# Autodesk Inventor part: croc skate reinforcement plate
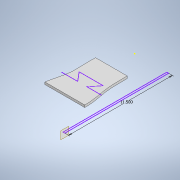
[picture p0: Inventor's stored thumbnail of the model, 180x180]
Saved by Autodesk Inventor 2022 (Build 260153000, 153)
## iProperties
Created: 2021-06
Part Number: croc skate reinforcement plate
Material: Generic
Document SubType Name: Modeling
Designer: garre
Density: 1 g/cm^3
Appearance: Default
Author: garre
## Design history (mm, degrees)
sketch "Sketch1"
  geometry: L1 (0, 0)-(0, 304.8); L2 (0, 0)-(76.2, 0); 16 further points
  constraints: 4 end point, 1 coincident, 1 horizontal, 1 point on line, 1 vertical, 15 other
  dimensions: "d0" = 25.4 distance from line of L1 point (25.4, 6.35); "d1" = 6.35 distance from line of L2 point (25.4, 6.35); "d2" = 31.75 distance from line of L1 point (-31.75, 19.05); "d3" = 19.05 distance from line of point (-31.75, 19.05) L2; "d4" = 44.45 distance from line of L1 point (44.45, 63.5); "d5" = 63.5 distance from line of L2 point (44.45, 63.5); "d6" = 76.2 distance of L1.start L2.end; "d7" = 304.8 distance of L1.start L1.end; "d8" = 44.45 distance from line of L1 point (-44.45, 88.9); "d9" = 88.9 distance from line of L2 point (-44.45, 88.9); "d10" = 50.8 distance from line of L1 point (-50.8, 152.4); "d11" = 152.4 distance from line of L2 point (-50.8, 152.4); "d12" = 44.45 distance from line of L1 point (44.45, 133.35); "d13" = 133.35 distance from line of L2 point (44.45, 133.35); "d14" = 57.15 distance from line of L1 point (57.15, 196.85); "d15" = 196.85 distance from line of L2 point (57.15, 196.85); "d16" = 50.8 distance from line of L1 point (-50.8, 222.25); "d17" = 222.25 distance from line of L2 point (-50.8, 222.25); "d18" = 31.75 distance from line of L1 point (-31.75, 260.35); "d19" = 260.35 distance from line of L2 point (-31.75, 260.35); "d20" = 57.15 distance from line of L1 point (57.15, 273.05); "d21" = 273.05 distance from line of L2 point (57.15, 273.05); "d22" = 285.75 distance from line of L2 point (0, 285.75); "d23" = 292.1 distance from line of L2 point (25.4, 292.1); "d24" = 19.05 distance from line of L1 point (-19.05, 273.05); "d25" = 273.05 distance from line of L2 point (-19.05, 273.05)
extrude "Extrusion1" new body sketch "Sketch1" distance "d26" = 25.4; taper "d27" = 0 deg
sketch "Sketch4"
  geometry: L1 (90.123, 0)-(95.236, 0); L2 (95.236, 0)-(95.236, 292.1); L3 (95.236, 292.1)-(90.123, 292.1); L4 (90.123, 292.1)-(90.123, 0); 1 further point
  constraints: 8 end point, 2 parallel, 1 horizontal, 1 perpendicular
  dimensions: "d33" = 292.1 distance of L1.end L2.end
workplane "Work Plane1"
sketch "Sketch5"
  geometry: L1 (292.1, -6.35)-(0, -6.35) reference; L2 (0, -6.35)-(0, 25.4); L3 (0, 25.4)-(292.1, 25.4); L4 (292.1, 25.4)-(292.1, -6.35); L5 (292.1, -6.35)-(0, -6.35); L6 (63.5, 12.7)-(254, 12.7); A1 r 165.1 centre (63.5, 177.8) between (0, 25.4) and (63.5, 12.7); A2 r 63.5 centre (254, 76.2) between (254, 12.7) and (292.1, 25.4); 1 further point
  constraints: 10 end point, 4 point on circle, 2 centre point, 2 perpendicular, 2 tangent, 1 horizontal, 1 vertical
  dimensions: "d36" = 31.75 distance of L1.end L2.end; "d37" = 190.5 distance of L6.start L6.end; "d38" = 38.1 distance from line of L4 L6.end; "d40" = 19.05 distance between parallel lines of L1 L6
extrude "Extrusion4" cut sketch "Sketch5" distance "d42" = 207.9625; taper "d43" = 0 deg
sketch "Sketch6"
  geometry: L1 (-20.786, 292.1)-(-25.4, 292.1) reference; L2 (-23.093, 292.1)-(0, 292.1); L3 (0, 292.1)-(-47.789, 292.1); L4 (54.325, 215.9)-(-70.012, 215.9); L5 (-70.012, 215.9)-(-70.012, 196.85); L6 (-70.012, 196.85)-(58.438, 196.85); L7 (58.438, 196.85)-(58.438, 215.9); L8 (58.438, 215.9)-(54.325, 215.9); L9 (49.579, 63.5)-(-58.622, 63.5); L10 (-58.622, 63.5)-(-58.622, 44.45); L11 (-58.622, 44.45)-(49.579, 44.45); L12 (49.579, 44.45)-(49.579, 63.5); 1 further point
  constraints: 22 end point, 7 perpendicular, 3 horizontal, 2 point on line, 1 midpoint
  dimensions: "d44" = 76.2 distance between parallel lines of L4 L2; "d45" = 19.05 distance between parallel lines of L6 L4; "d46" = 19.05 distance of L9.end L10.end; "d47" = 44.45 vertical distance of point (0, 0) L11.end
extrude "Extrusion5" cut sketch "Sketch6" distance "d48" = 5.08; taper "d49" = 0 deg
feature "FaceDraft1" dims angle "d50" = 15 deg
feature "FaceDraft2" dims angle "d51" = 15 deg
feature "FaceDraft3" dims angle "d52" = 15 deg
feature "FaceDraft4" dims angle "d53" = 15 deg
sketch "Sketch7"
  geometry: L1 (12.7, 147.902)-(34.013, 122.502); L2 (-12.7, 147.902)-(-34.013, 122.502); L3 (34.013, 122.502)-(-34.013, 122.502); L4 (-12.7, 147.902)-(-58.181, 147.902); L5 (12.7, 147.902)-(54.892, 147.902); 1 further point
  constraints: 10 end point, 2 horizontal
sketch "Sketch9"
  geometry: L1 (2.54, 80.429)-(-2.54, 80.429); L2 (-2.54, 80.429)-(-2.54, 24.539); L3 (-2.54, 24.539)-(2.54, 24.539); L4 (2.54, 24.539)-(2.54, 80.429); L5 (0, 0)-(-12.229, 0) reference; L6 (0, 0)-(0, -2.992)
  constraints: 10 end point, 2 parallel, 1 horizontal, 1 perpendicular, 1 vertical
  dimensions: "d65" = 5.08 distance of L3.end L2.end; "d66" = 55.88937 distance of L3.end L1.start; "d67" = 2.54 distance between parallel lines of L6 L4
extrude "Extrusion7" join sketch "Sketch9" distance "d68" = 5.08; taper "d69" = 0 deg
sketch "Sketch10"
  geometry: L1 (0, 0)-(-12.229, 0) reference; L2 (0, 0)-(0, -7.512); L3 (2.54, 223.005)-(-2.54, 223.005); L4 (-2.54, 223.005)-(-2.54, 186.193); L5 (-2.54, 186.193)-(2.54, 186.193); L6 (2.54, 186.193)-(2.54, 223.005); L7 (-20.786, 292.1)-(-25.4, 292.1) reference
  constraints: 10 end point, 2 parallel, 1 horizontal, 1 perpendicular, 1 vertical
  dimensions: "d70" = 69.09509 distance between parallel lines of L7 L3; "d71" = 2.54 distance between parallel lines of L2 L6; "d72" = 5.08 distance between parallel lines of L6 L4
extrude "Extrusion8" join sketch "Sketch10" distance "d73" = 5.08; taper "d74" = 0 deg
sketch "Sketch11"
  geometry: L1 (-44.45, 63.5)-(43.867, 63.5) reference; L2 (54.838, 196.85)-(-57.15, 196.85) reference; L3 (-56.879, 195.326)-(54.9, 195.326); L4 (-44.56, 65.024)-(43.947, 65.024); 1 further point
  constraints: 4 end point, 1 horizontal, 1 parallel, 6 other
  dimensions: "d75" = 1.524 distance between parallel lines of L1 L4; "d76" = 1.524 distance between parallel lines of L2 L3
extrude "Extrusion9" join sketch "Sketch11" distance "d77" = 6.35; taper "d78" = 0 deg
sketch "Sketch12"
  geometry: L1 (134.929, 339.896)-(-123.741, 339.896); L2 (-123.741, 339.896)-(-123.741, -55.269); L3 (-123.741, -55.269)-(134.929, -55.269); L4 (134.929, -55.269)-(134.929, 339.896); 1 further point
  constraints: 8 end point, 2 parallel, 1 horizontal, 1 perpendicular
extrude "Extrusion10" cut sketch "Sketch12" extent not by distance; stored distance "d79" = 0; taper "d80" = 0 deg
sketch "Sketch13"
  geometry: L1 (7.249, 229.551)-(-9.885, 229.551); L2 (-9.885, 229.551)-(-9.885, 16.475); L3 (-9.885, 16.475)-(7.249, 16.475); L4 (7.249, 16.475)-(7.249, 229.551); 1 further point
  constraints: 8 end point, 2 parallel, 1 horizontal, 1 perpendicular
extrude "Extrusion11" cut sketch "Sketch13" extent not by distance; stored distance "d81" = 0; taper "d82" = 0 deg
sketch "Sketch14"
  geometry: L1 (16.036, 253.714)-(-27.458, 253.714); L2 (-27.458, 253.714)-(-27.458, 118.4); L3 (-27.458, 118.4)-(16.036, 118.4); L4 (16.036, 118.4)-(16.036, 253.714); 1 further point
  constraints: 8 end point, 2 parallel, 1 horizontal, 1 perpendicular
extrude "Extrusion12" cut sketch "Sketch14" distance "d83" = 25.4; taper "d84" = 0 deg
body "Solid1"
node "Projected Loop1"
body "Solid2"
body "Solid3"
other parameters: "d54" = 25.4, "d55" = 12.7
